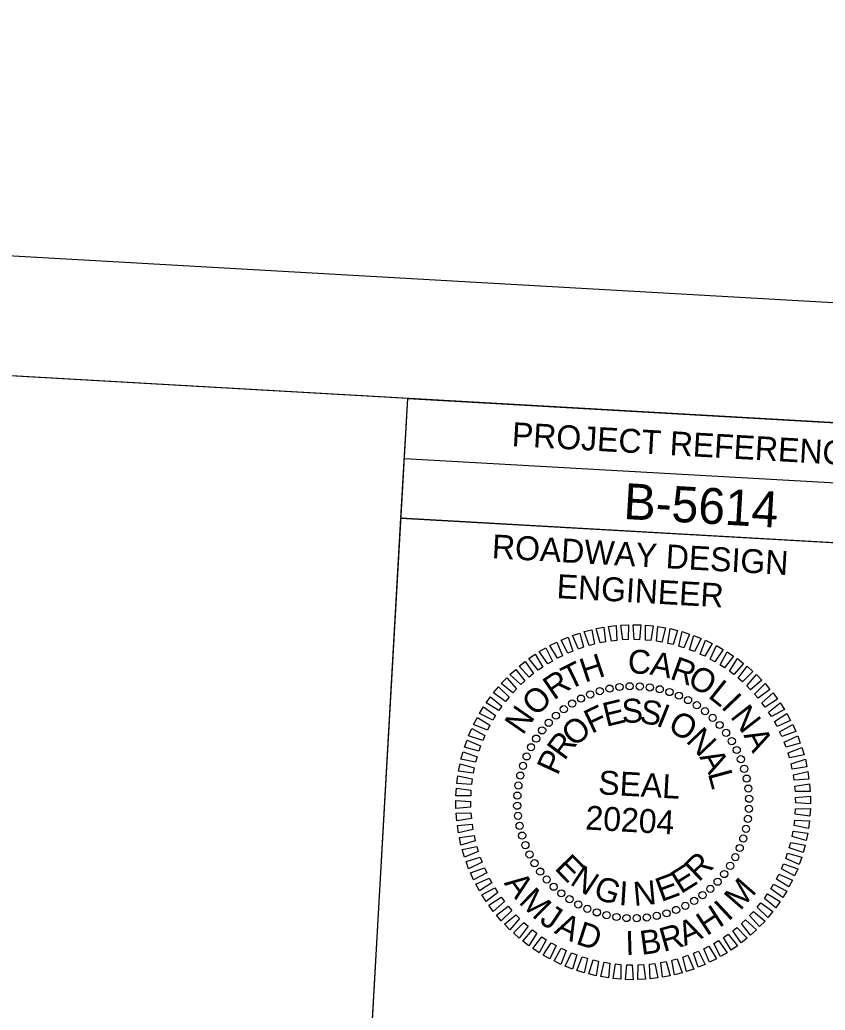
# Model space of a CAD drawing. Extents: x 2602909 to 2604669, y 617940 to 619640.
# Drawn here: x 2604361.6 to 2604530, y 618898.1 to 619105.1 of the extents above; entities that cross this region are included whole.
import ezdxf

# ---------------------------------------------------------------- set-up
doc = ezdxf.new("R2010")
doc.units = 0
for name, color, linetype in [('Default', 7, 'Continuous'), ('Scratch_Level_1', 7, 'Continuous'), ('Sheet Data Field CELL', 7, 'Continuous'), ('Sheet PE Seal Cell', 7, 'Continuous'), ('Sheet Plan And Profile CELL', 7, 'Continuous'), ('Stewart Plot Border Xerox6279 and LJ5000', 7, 'Continuous')]:
    doc.layers.add(name, color=color, linetype=linetype)

msp = doc.modelspace()

# ---------------------------------------------------------------- linework, layer by layer
at = {"layer": 'Scratch_Level_1'}
msp.add_lwpolyline([(2604574.88, 618817.07), (2604431.33, 618825.24), (2604442.75, 619025.97), (2603144.9, 619099.88), (2603085.2, 618051.58), (2604526.6, 617969.49)], close=True, dxfattribs=at)
msp.add_lwpolyline([(2604574.88, 618817.07), (2604431.33, 618825.24), (2604442.75, 619025.97), (2603144.9, 619099.88), (2603085.2, 618051.58), (2604526.6, 617969.49)], close=True, dxfattribs=at)
at = {"layer": 'Sheet PE Seal Cell'}
msp.add_line((2604489.88, 618941.56), (2604489.88, 618941.56), dxfattribs=at)
for points in [[(2604478.42, 618973.57), (2604477.2, 618976.44), (2604478.74, 618976.93), (2604479.5, 618973.94)], [(2604480.68, 618974.29), (2604479.66, 618977.24), (2604481.23, 618977.62), (2604481.78, 618974.58)], [(2604482.99, 618974.85), (2604482.17, 618977.86), (2604483.77, 618978.13), (2604484.11, 618975.07)], [(2604485.33, 618975.25), (2604484.72, 618978.31), (2604486.33, 618978.47), (2604486.46, 618975.39)], [(2604487.69, 618975.48), (2604487.3, 618978.58), (2604488.92, 618978.63), (2604488.83, 618975.55)], [(2604490.06, 618975.55), (2604489.89, 618978.67), (2604491.5, 618978.61), (2604491.2, 618975.54)], [(2604492.43, 618975.46), (2604492.48, 618978.58), (2604494.08, 618978.4), (2604493.57, 618975.36)], [(2604494.79, 618975.2), (2604495.05, 618978.31), (2604496.64, 618978.02), (2604495.91, 618975.02)], [(2604497.12, 618974.77), (2604497.6, 618977.86), (2604499.17, 618977.46), (2604498.23, 618974.52)], [(2604499.42, 618974.19), (2604500.12, 618977.23), (2604501.65, 618976.72), (2604500.51, 618973.86)], [(2604474.08, 618971.66), (2604472.47, 618974.33), (2604473.92, 618975.03), (2604475.1, 618972.18)], [(2604476.22, 618972.69), (2604474.8, 618975.47), (2604476.3, 618976.06), (2604477.27, 618973.14)], [(2604501.67, 618973.44), (2604502.58, 618976.43), (2604504.08, 618975.82), (2604502.74, 618973.04)], [(2604503.87, 618972.54), (2604504.98, 618975.46), (2604506.43, 618974.74), (2604504.9, 618972.06)], [(2604472.02, 618970.48), (2604470.22, 618973.04), (2604471.63, 618973.84), (2604473, 618971.07)], [(2604505.99, 618971.49), (2604507.31, 618974.32), (2604508.7, 618973.51), (2604506.99, 618970.94)], [(2604508.04, 618970.3), (2604509.55, 618973.03), (2604510.89, 618972.12), (2604509, 618969.68)], [(2604468.17, 618967.72), (2604466.04, 618970), (2604467.31, 618970.98), (2604469.05, 618968.44)], [(2604470.04, 618969.17), (2604468.08, 618971.59), (2604469.42, 618972.49), (2604470.98, 618969.82)], [(2604510, 618968.96), (2604511.7, 618971.58), (2604512.97, 618970.58), (2604510.92, 618968.27)], [(2604466.4, 618966.14), (2604464.11, 618968.26), (2604465.32, 618969.34), (2604467.23, 618966.92)], [(2604511.86, 618967.49), (2604513.74, 618969.98), (2604514.93, 618968.9), (2604512.73, 618966.74)], [(2604464.74, 618964.44), (2604462.31, 618966.4), (2604463.44, 618967.56), (2604465.52, 618965.28)], [(2604513.62, 618965.89), (2604515.66, 618968.25), (2604516.78, 618967.08), (2604514.43, 618965.09)], [(2604515.26, 618964.18), (2604517.46, 618966.39), (2604518.49, 618965.14), (2604516.01, 618963.32)], [(2604463.2, 618962.63), (2604460.65, 618964.42), (2604461.69, 618965.65), (2604463.92, 618963.52)], [(2604516.77, 618962.35), (2604519.13, 618964.4), (2604520.07, 618963.09), (2604517.46, 618961.44)], [(2604461.8, 618960.72), (2604459.12, 618962.32), (2604460.08, 618963.62), (2604462.45, 618961.66)], [(2604518.16, 618960.42), (2604520.65, 618962.31), (2604521.5, 618960.93), (2604518.78, 618959.47)], [(2604460.53, 618958.71), (2604457.75, 618960.13), (2604458.61, 618961.49), (2604461.12, 618959.69)], [(2604459.41, 618956.62), (2604456.53, 618957.84), (2604457.3, 618959.26), (2604459.92, 618957.64)], [(2604519.41, 618958.41), (2604522.02, 618960.11), (2604522.77, 618958.68), (2604519.96, 618957.41)], [(2604458.43, 618954.46), (2604455.48, 618955.47), (2604456.14, 618956.95), (2604458.88, 618955.51)], [(2604520.51, 618956.3), (2604523.24, 618957.82), (2604523.89, 618956.34), (2604520.99, 618955.27)], [(2604457.61, 618952.24), (2604454.59, 618953.04), (2604455.15, 618954.56), (2604457.98, 618953.32)], [(2604521.46, 618954.13), (2604524.29, 618955.46), (2604524.83, 618953.93), (2604521.87, 618953.07)], [(2604456.94, 618949.96), (2604453.88, 618950.55), (2604454.33, 618952.1), (2604457.24, 618951.06)], [(2604522.26, 618951.9), (2604525.17, 618953.02), (2604525.61, 618951.47), (2604522.6, 618950.81)], [(2604522.9, 618949.61), (2604525.89, 618950.53), (2604526.21, 618948.95), (2604523.16, 618948.5)], [(2604456.44, 618947.64), (2604453.34, 618948.02), (2604453.68, 618949.6), (2604456.65, 618948.76)], [(2604523.38, 618947.29), (2604526.42, 618948), (2604526.64, 618946.4), (2604523.57, 618946.16)], [(2604456.09, 618945.29), (2604452.98, 618945.45), (2604453.21, 618947.05), (2604456.23, 618946.43)], [(2604455.92, 618942.93), (2604452.8, 618942.87), (2604452.92, 618944.48), (2604455.97, 618944.07)], [(2604523.7, 618944.94), (2604526.78, 618945.43), (2604526.89, 618943.82), (2604523.8, 618943.8)], [(2604455.9, 618940.55), (2604452.8, 618940.28), (2604452.8, 618941.89), (2604455.88, 618941.7)], [(2604523.86, 618942.57), (2604526.96, 618942.85), (2604526.96, 618941.23), (2604523.88, 618941.43)], [(2604523.84, 618940.2), (2604526.96, 618940.26), (2604526.84, 618938.65), (2604523.79, 618939.06)], [(2604456.06, 618938.19), (2604452.98, 618937.69), (2604452.87, 618939.31), (2604455.96, 618939.33)], [(2604523.67, 618937.83), (2604526.78, 618937.68), (2604526.55, 618936.08), (2604523.53, 618936.7)], [(2604456.38, 618935.84), (2604453.34, 618935.13), (2604453.12, 618936.73), (2604456.19, 618936.96)], [(2604523.32, 618935.49), (2604526.42, 618935.11), (2604526.08, 618933.53), (2604523.11, 618934.37)], [(2604456.86, 618933.51), (2604453.87, 618932.6), (2604453.55, 618934.18), (2604456.6, 618934.63)], [(2604457.5, 618931.23), (2604454.59, 618930.11), (2604454.15, 618931.66), (2604457.16, 618932.32)], [(2604522.82, 618933.17), (2604525.88, 618932.58), (2604525.43, 618931.03), (2604522.52, 618932.06)], [(2604458.3, 618929), (2604455.47, 618927.67), (2604454.93, 618929.19), (2604457.89, 618930.06)], [(2604522.15, 618930.89), (2604525.17, 618930.09), (2604524.61, 618928.57), (2604521.78, 618929.81)], [(2604459.25, 618926.82), (2604456.52, 618925.31), (2604455.87, 618926.79), (2604458.77, 618927.86)], [(2604521.33, 618928.67), (2604524.28, 618927.66), (2604523.62, 618926.18), (2604520.88, 618927.61)], [(2604460.35, 618924.72), (2604457.74, 618923.02), (2604456.99, 618924.45), (2604459.8, 618925.72)], [(2604520.35, 618926.5), (2604523.23, 618925.29), (2604522.46, 618923.87), (2604519.84, 618925.49)], [(2604461.6, 618922.7), (2604459.11, 618920.82), (2604458.26, 618922.2), (2604460.98, 618923.66)], [(2604519.23, 618924.42), (2604522.01, 618923), (2604521.15, 618921.64), (2604518.64, 618923.43)], [(2604462.99, 618920.78), (2604460.63, 618918.73), (2604459.69, 618920.04), (2604462.3, 618921.69)], [(2604517.96, 618922.41), (2604520.64, 618920.81), (2604519.68, 618919.5), (2604517.31, 618921.47)], [(2604464.5, 618918.95), (2604462.3, 618916.74), (2604461.27, 618917.98), (2604463.75, 618919.81)], [(2604516.56, 618920.5), (2604519.11, 618918.71), (2604518.07, 618917.48), (2604515.84, 618919.61)], [(2604466.14, 618917.24), (2604464.1, 618914.88), (2604462.98, 618916.05), (2604465.33, 618918.04)], [(2604513.36, 618916.99), (2604515.65, 618914.87), (2604514.44, 618913.79), (2604512.53, 618916.21)], [(2604515.02, 618918.69), (2604517.45, 618916.73), (2604516.32, 618915.57), (2604514.24, 618917.85)], [(2604467.9, 618915.64), (2604466.02, 618913.14), (2604464.83, 618914.23), (2604467.03, 618916.39)], [(2604469.76, 618914.17), (2604468.06, 618911.55), (2604466.79, 618912.55), (2604468.84, 618914.86)], [(2604511.59, 618915.41), (2604513.72, 618913.13), (2604512.45, 618912.14), (2604510.71, 618914.69)], [(2604471.72, 618912.83), (2604470.21, 618910.1), (2604468.87, 618911.01), (2604470.76, 618913.45)], [(2604507.74, 618912.64), (2604509.54, 618910.09), (2604508.13, 618909.29), (2604506.76, 618912.05)], [(2604509.72, 618913.96), (2604511.68, 618911.54), (2604510.34, 618910.64), (2604508.78, 618913.3)], [(2604473.77, 618911.64), (2604472.45, 618908.81), (2604471.06, 618909.62), (2604472.77, 618912.19)], [(2604475.89, 618910.58), (2604474.78, 618907.67), (2604473.33, 618908.38), (2604474.86, 618911.07)], [(2604505.68, 618911.47), (2604507.29, 618908.8), (2604505.84, 618908.1), (2604504.66, 618910.95)], [(2604478.09, 618909.68), (2604477.18, 618906.7), (2604475.68, 618907.31), (2604477.02, 618910.09)], [(2604480.34, 618908.94), (2604479.64, 618905.9), (2604478.11, 618906.4), (2604479.25, 618909.27)], [(2604482.64, 618908.35), (2604482.16, 618905.27), (2604480.59, 618905.67), (2604481.53, 618908.61)], [(2604499.08, 618908.84), (2604500.1, 618905.89), (2604498.53, 618905.51), (2604497.98, 618908.54)], [(2604501.34, 618909.56), (2604502.56, 618906.69), (2604501.02, 618906.2), (2604500.26, 618909.19)], [(2604503.54, 618910.44), (2604504.96, 618907.66), (2604503.46, 618907.06), (2604502.49, 618909.99)], [(2604484.97, 618907.93), (2604484.71, 618904.82), (2604483.12, 618905.11), (2604483.85, 618908.11)], [(2604487.33, 618907.67), (2604487.28, 618904.55), (2604485.68, 618904.73), (2604486.19, 618907.77)], [(2604489.7, 618907.57), (2604489.87, 618904.46), (2604488.26, 618904.52), (2604488.56, 618907.59)], [(2604492.07, 618907.64), (2604492.46, 618904.55), (2604490.84, 618904.5), (2604490.93, 618907.58)], [(2604494.43, 618907.88), (2604495.04, 618904.82), (2604493.43, 618904.66), (2604493.3, 618907.74)], [(2604496.77, 618908.28), (2604497.59, 618905.27), (2604495.99, 618904.99), (2604495.65, 618908.06)]]:
    msp.add_lwpolyline(points, close=True, dxfattribs=at)
for centre in [(2604487.03, 618965.65), (2604489.14, 618965.8), (2604491.26, 618965.77), (2604480.9, 618964.09), (2604482.9, 618964.79), (2604484.95, 618965.31), (2604493.36, 618965.56), (2604495.44, 618965.17), (2604497.48, 618964.59), (2604499.46, 618963.84), (2604477.12, 618962.19), (2604478.97, 618963.22), (2604501.36, 618962.92), (2604503.18, 618961.84), (2604473.74, 618959.66), (2604475.37, 618961), (2604504.9, 618960.61), (2604472.22, 618958.18), (2604506.5, 618959.22), (2604507.97, 618957.71), (2604470.84, 618956.58), (2604509.31, 618956.07), (2604469.6, 618954.86), (2604510.5, 618954.32), (2604467.6, 618951.14), (2604468.52, 618953.05), (2604511.54, 618952.48), (2604466.85, 618949.16), (2604512.41, 618950.55), (2604466.28, 618947.13), (2604513.1, 618948.55), (2604465.88, 618945.05), (2604513.62, 618946.5), (2604465.67, 618942.94), (2604513.96, 618944.41), (2604465.64, 618940.83), (2604514.12, 618942.3), (2604465.8, 618938.72), (2604514.09, 618940.19), (2604466.14, 618936.63), (2604513.88, 618938.08), (2604466.66, 618934.58), (2604513.48, 618936), (2604467.35, 618932.58), (2604512.91, 618933.97), (2604468.22, 618930.65), (2604512.16, 618931.99), (2604469.26, 618928.81), (2604511.24, 618930.08), (2604470.45, 618927.06), (2604508.92, 618926.55), (2604510.16, 618928.26), (2604471.79, 618925.42), (2604507.54, 618924.95), (2604473.26, 618923.9), (2604474.86, 618922.52), (2604506.02, 618923.47), (2604476.58, 618921.29), (2604478.4, 618920.2), (2604502.64, 618920.94), (2604504.39, 618922.13), (2604480.3, 618919.28), (2604482.28, 618918.54), (2604496.86, 618918.34), (2604498.86, 618919.04), (2604500.79, 618919.91), (2604484.32, 618917.96), (2604486.4, 618917.57), (2604488.5, 618917.35), (2604490.62, 618917.33), (2604492.73, 618917.48), (2604494.81, 618917.82)]:
    msp.add_circle(centre, 0.75, dxfattribs=at)
at = {"layer": 'Sheet Plan And Profile CELL'}
msp.add_line((2604442.04, 619013.44), (2604641.76, 619002.06), dxfattribs=at)
for points in [[(2604642.48, 619014.59), (2603144.9, 619099.88), (2603085.2, 618051.58), (2604582.77, 617966.29)], [(2604442.75, 619025.97), (2604642.48, 619014.59), (2604641.05, 618989.58), (2604441.33, 619000.96)], [(2604441.33, 619000.96), (2604541.21, 618995.27), (2604534.82, 618882.94), (2604434.94, 618888.65)]]:
    msp.add_lwpolyline(points, close=True, dxfattribs=at)
at = {"layer": 'Stewart Plot Border Xerox6279 and LJ5000'}
msp.add_lwpolyline([(2602909.06, 618036.57), (2604606.31, 617939.91), (2604668.86, 619038.13), (2602971.61, 619134.8)], close=True, dxfattribs=at)

# ---------------------------------------------------------------- texts
at = {"layer": 'Default'}
for s, height, p in [('ROADWAY DESIGN', 5.0001, (2604460.25, 618992.57)), ('ENGINEER', 5, (2604473.79, 618984.25))]:
    msp.add_text(s, height=height, rotation=356.7403, dxfattribs=at).set_placement(p)
at = {"layer": 'Sheet Data Field CELL'}
msp.add_text('B-5614', height=7.5, rotation=356.7403, dxfattribs=at).set_placement((2604487.75, 619000.79))
at = {"layer": 'Sheet PE Seal Cell'}
for s, rotation, p in [('H', 18.3413, (2604479.76, 618966.52)), ('C', 358.7021, (2604488.74, 618968.47)), ('A', 349.197, (2604493.2, 618968.29)), ('T', 26.1305, (2604476.47, 618964.92)), ('R', 340.1496, (2604497.36, 618967.44)), ('R', 34.3392, (2604473.28, 618962.77)), ('O', 331.9409, (2604500.98, 618966.1)), ('L', 321.2157, (2604505.35, 618963.61)), ('O', 45.0643, (2604469.62, 618959.31)), ('I', 313.7506, (2604508.08, 618961.41)), ('E', 13.7262, (2604484.24, 618957.3)), ('S', 1.964, (2604487.56, 618958.12)), ('S', 350.005, (2604491.04, 618958.24)), ('N', 55.2748, (2604466.79, 618955.43)), ('F', 25.4042, (2604481.17, 618955.83)), ('I', 338.0461, (2604494.47, 618957.64)), ('O', 329.2906, (2604496.87, 618956.75)), ('N', 307.8106, (2604510.04, 618959.42)), ('O', 41.2129, (2604477.61, 618952.92)), ('R', 53.3124, (2604475.5, 618950.09)), ('N', 313.4818, (2604500.74, 618954.27)), ('A', 297.6002, (2604512.89, 618955.57)), ('P', 65.0746, (2604474.07, 618946.98)), ('A', 298.4318, (2604503.67, 618951.02)), ('SEAL', 356.7403, (2604482.49, 618943.24)), ('L', 285.0959, (2604505.48, 618947.58)), ('20204', 356.7403, (2604479.79, 618935.88)), ('E', 314.5909, (2604473.25, 618927.63)), ('R', 43.7832, (2604503.58, 618924.74)), ('N', 326.3531, (2604476.44, 618924.53)), ('E', 32.021, (2604499.86, 618922.3)), ('A', 306.4872, (2604462.76, 618924.63)), ('G', 341.4032, (2604481.33, 618921.63)), ('I', 356.4532, (2604486.8, 618920.09)), ('N', 5.2087, (2604490.1, 618919.87)), ('E', 20.2587, (2604495.73, 618920.67)), ('M', 48.9297, (2604512.26, 618918.73)), ('M', 315.5347, (2604465.76, 618920.58)), ('I', 42.9898, (2604509.77, 618916.53)), ('J', 326.2408, (2604470.07, 618916.46)), ('H', 33.2369, (2604505.25, 618913.52)), ('A', 333.0787, (2604473.2, 618914.28)), ('A', 24.1894, (2604500.65, 618911.46)), ('D', 342.1262, (2604477.7, 618912)), ('I', 1.6987, (2604488.31, 618909.63)), ('B', 7.6386, (2604491.62, 618909.64)), ('R', 15.9807, (2604496.24, 618910.23))]:
    msp.add_text(s, height=5, rotation=rotation, dxfattribs=at).set_placement(p)
at = {"layer": 'Sheet Plan And Profile CELL'}
msp.add_text('PROJECT REFERENCE NO.', height=5.0001, rotation=356.7403, dxfattribs=at).set_placement((2604464.42, 619016.02))

doc.saveas('drawing.dxf')
